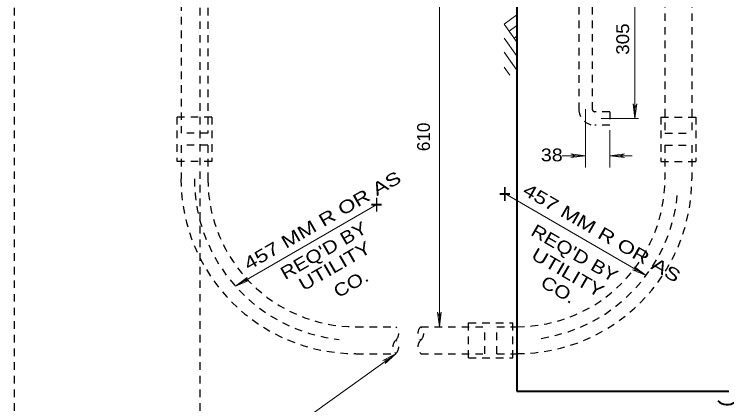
# Model space of a CAD drawing. Extents: x 312583 to 312854, y 144419 to 144597.
# Drawn here: x 312628.46 to 312670.78, y 144489.77 to 144512.97 of the extents above; entities that cross this region are included whole.
import ezdxf
from ezdxf.enums import TextEntityAlignment as Align

# ---------------------------------------------------------------- set-up
doc = ezdxf.new("R2010")
doc.units = 0
doc.header["$LTSCALE"] = 0.3
doc.linetypes.add('SHORT_DASHED', pattern=[2.7, 1.5, -1.2])
doc.layers.add('1', color=7, linetype='Continuous', lineweight=25)
doc.layers.add('2', color=7, linetype='Continuous', lineweight=13)

msp = doc.modelspace()

# ---------------------------------------------------------------- linework, layer by layer
at = {"layer": '1', "linetype": 'SHORT_DASHED'}
for p, q in [((312638.37, 144534.6773), (312638.37, 144505.9043)), ((312667.1046, 144517.8796), (312667.1046, 144505.9043)), ((312668.6993, 144517.8796), (312668.6993, 144505.9043)), ((312639.9646, 144517.4043), (312639.9646, 144505.9043)), ((312661.991, 144515.8326), (312661.991, 144507.3303)), ((312662.7883, 144515.8403), (312662.7883, 144507.3303)), ((312640.2023, 144506.8626), (312638.1246, 144506.8626)), ((312638.1246, 144506.8626), (312638.1246, 144504.2253)), ((312640.2023, 144506.8626), (312640.2023, 144504.2253)), ((312663.831, 144507.177), (312662.9493, 144507.177)), ((312663.831, 144507.177), (312663.831, 144506.372)), ((312666.867, 144506.8626), (312668.937, 144506.8626)), ((312666.867, 144506.8626), (312666.867, 144504.2253)), ((312668.937, 144506.8626), (312668.937, 144504.2253)), ((312663.831, 144506.372), (312662.9493, 144506.372)), ((312639.9646, 144505.9043), (312638.37, 144505.9043)), ((312667.1046, 144505.9043), (312668.6993, 144505.9043)), ((312639.9646, 144505.1836), (312638.37, 144505.1836)), ((312638.37, 144505.1836), (312638.37, 144503.1826)), ((312639.9646, 144505.1836), (312639.9646, 144503.1826)), ((312667.1046, 144505.1836), (312668.6993, 144505.1836)), ((312667.1046, 144505.1836), (312667.1046, 144503.1826)), ((312668.6993, 144505.1836), (312668.6993, 144503.1826)), ((312640.2023, 144504.2253), (312638.1246, 144504.2253)), ((312666.867, 144504.2253), (312668.937, 144504.2253)), ((312655.4436, 144492.5643), (312655.4436, 144494.642)), ((312655.4436, 144494.642), (312658.081, 144494.642)), ((312658.081, 144492.5643), (312658.081, 144494.642)), ((312648.7506, 144494.4043), (312651.1273, 144494.4043)), ((312652.607, 144494.4043), (312656.402, 144494.4043)), ((312656.402, 144492.802), (312656.402, 144494.4043)), ((312657.1226, 144494.4043), (312658.3186, 144494.4043)), ((312657.1226, 144492.802), (312657.1226, 144494.4043)), ((312648.7506, 144492.802), (312651.1273, 144492.802)), ((312652.607, 144492.802), (312656.402, 144492.802)), ((312655.4436, 144492.5643), (312658.081, 144492.5643)), ((312657.1226, 144492.802), (312658.3186, 144492.802))]:
    msp.add_line(p, q, dxfattribs=at)
at = {"layer": '1', "lineweight": 40}
for p, q in [((312658.3186, 144518.3626), (312658.3186, 144490.571)), ((312658.3186, 144490.571), (312670.8996, 144490.571))]:
    msp.add_line(p, q, dxfattribs=at)
at = {"layer": '1', "linetype": 'SHORT_DASHED'}
for centre, radius, start, end in [((312662.9503, 144507.3341), 0.9583, 180, 270), ((312662.9503, 144507.3341), 0.16, 180, 270), ((312648.7487, 144503.1865), 10.3816, 180, 270), ((312648.7487, 144503.1865), 9.5833, 180, 264.11531), ((312648.7487, 144503.1865), 8.785, 180, 270), ((312658.3186, 144503.1865), 10.3816, 270, 0), ((312658.3186, 144503.1865), 8.785, 270, 0), ((312658.3186, 144503.1865), 9.5833, 278.67864, 356.01524), ((312650.7536, 144494.0023), 0.5448, 312.89063, 47.10936), ((312652.9787, 144494.0023), 0.5448, 132.89064, 227.10937), ((312652.2371, 144494.0023), 0.5448, 312.89063, 47.10936), ((312651.4952, 144493.204), 0.5448, 132.89064, 227.10937), ((312650.7536, 144493.204), 0.5448, 312.89063, 47.10936), ((312652.9787, 144493.204), 0.5448, 132.89064, 227.10937)]:
    msp.add_arc(centre, radius, start, end, dxfattribs=at)
at = {"layer": '1', "lineweight": 40}
msp.add_arc((312670.8004, 144490.5843), 0.8027, 225.84295, 305.84934, dxfattribs=at)
at = {"layer": '2', "linetype": 'SHORT_DASHED', "lineweight": 25}
for p, q in [((312628.4646, 144517.4043), (312628.4646, 144485.2886)), ((312639.4816, 144517.4043), (312639.4816, 144485.2886))]:
    msp.add_line(p, q, dxfattribs=at)
at = {"layer": '2'}
for p, q in [((312653.711, 144517.4043), (312653.711, 144494.4043)), ((312665.326, 144506.7706), (312665.326, 144517.3046)), ((312658.3186, 144512.927), (312657.5596, 144512.3826)), ((312657.5596, 144512.3826), (312658.334, 144511.294)), ((312658.3186, 144512.2983), (312657.851, 144511.9686)), ((312657.5596, 144511.5546), (312658.2956, 144510.512)), ((312658.3186, 144511.6696), (312658.15, 144511.547)), ((312657.5596, 144510.7113), (312658.3186, 144509.638)), ((312657.5596, 144509.8296), (312657.9046, 144509.3466)), ((312662.3896, 144507.3303), (312662.3896, 144503.8718)), ((312665.2186, 144507.637), (312665.326, 144507.361)), ((312665.326, 144506.7706), (312665.2186, 144507.637)), ((312665.4333, 144507.637), (312665.326, 144507.361)), ((312665.326, 144506.7706), (312665.4333, 144507.637)), ((312663.3173, 144506.7706), (312665.5406, 144506.7706)), ((312663.831, 144506.0883), (312663.831, 144503.8718)), ((312661.0035, 144504.5626), (312662.3896, 144504.5626)), ((312661.5232, 144504.67), (312661.7992, 144504.5626)), ((312662.3896, 144504.5626), (312661.5232, 144504.67)), ((312661.5232, 144504.4553), (312661.7992, 144504.5626)), ((312662.3896, 144504.5626), (312661.5232, 144504.4553)), ((312663.831, 144504.5626), (312664.6974, 144504.67)), ((312663.831, 144504.5626), (312664.6974, 144504.4553)), ((312663.831, 144504.5626), (312665.1679, 144504.5626)), ((312664.6974, 144504.67), (312664.4214, 144504.5626)), ((312664.6974, 144504.4553), (312664.4214, 144504.5626)), ((312665.993, 144497.4403), (312657.598, 144502.3086)), ((312641.5976, 144496.804), (312649.9926, 144501.6723)), ((312665.2953, 144497.9693), (312665.4793, 144497.7393)), ((312665.993, 144497.4403), (312665.2953, 144497.9693)), ((312665.188, 144497.7853), (312665.4793, 144497.7393)), ((312665.993, 144497.4403), (312665.188, 144497.7853)), ((312641.5976, 144496.804), (312642.2953, 144497.333)), ((312641.5976, 144496.804), (312642.4026, 144497.149)), ((312642.2953, 144497.333), (312642.1113, 144497.103)), ((312642.4026, 144497.149), (312642.1113, 144497.103)), ((312653.6036, 144495.2706), (312653.711, 144494.9946)), ((312653.711, 144494.4043), (312653.6036, 144495.2706)), ((312653.8183, 144495.2706), (312653.711, 144494.9946)), ((312653.711, 144494.4043), (312653.8183, 144495.2706)), ((312646.2896, 144489.329), (312651.1273, 144492.802)), ((312651.1273, 144492.802), (312650.3606, 144492.388)), ((312650.3606, 144492.388), (312650.6443, 144492.457)), ((312651.1273, 144492.802), (312650.4833, 144492.2116)), ((312650.4833, 144492.2116), (312650.6443, 144492.457))]:
    msp.add_line(p, q, dxfattribs=at)

# ---------------------------------------------------------------- texts
for s, rotation, width, p in [('305', 90, 1.1, (312664.9766, 144510.5614)), ('457 MM R OR AS', 30.108, 1.3, (312642.3767, 144497.7317)), ('457 MM R OR AS', 329.89, 1.3, (312658.5981, 144502.3019)), ("REQ'D BY", 30.112, 1.2, (312644.5524, 144497.1707)), ("REQ'D BY", 329.89, 1.2, (312659.0785, 144499.8813)), ('UTILITY', 30.113, 1.25, (312645.6431, 144496.5009)), ('UTILITY', 329.89, 1.25, (312659.1069, 144498.477)), ('CO.', 30.087, 1.2, (312647.708, 144496.0908)), ('CO.', 329.89, 1.2, (312659.6547, 144496.8252))]:
    msp.add_text(s, height=0.76, rotation=rotation, dxfattribs=dict(at, width=width)).set_placement(p)
msp.add_text('610', height=0.76, rotation=90, dxfattribs=at).set_placement((312653.1489, 144504.8347))
at = {"layer": '2', "width": 1.15}
msp.add_text('38 ', height=0.76, dxfattribs=at).set_placement((312659.7356, 144504.2301))
at = {"layer": '2', "width": 0.8}
for p in [(312657.5979, 144501.7183), (312649.9849, 144501.082)]:
    msp.add_text('+', height=1.177, rotation=359.999, dxfattribs=at).set_placement(p, align=Align.CENTER)

doc.saveas('drawing.dxf')
